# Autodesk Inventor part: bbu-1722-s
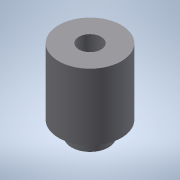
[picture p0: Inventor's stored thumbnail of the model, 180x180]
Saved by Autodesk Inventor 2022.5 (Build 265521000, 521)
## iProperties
Created: 2017-08
Part Number: bbu-1722-s
Material: 一般
Document SubType Name: Modeling
Designer: imaocorp
Density: 1 g/cm^3
Appearance: 既定
Author: imaocorp
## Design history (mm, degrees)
node "bbu-1722-s.x_t1"
node "bbu-1722-s"
node "Base1"
